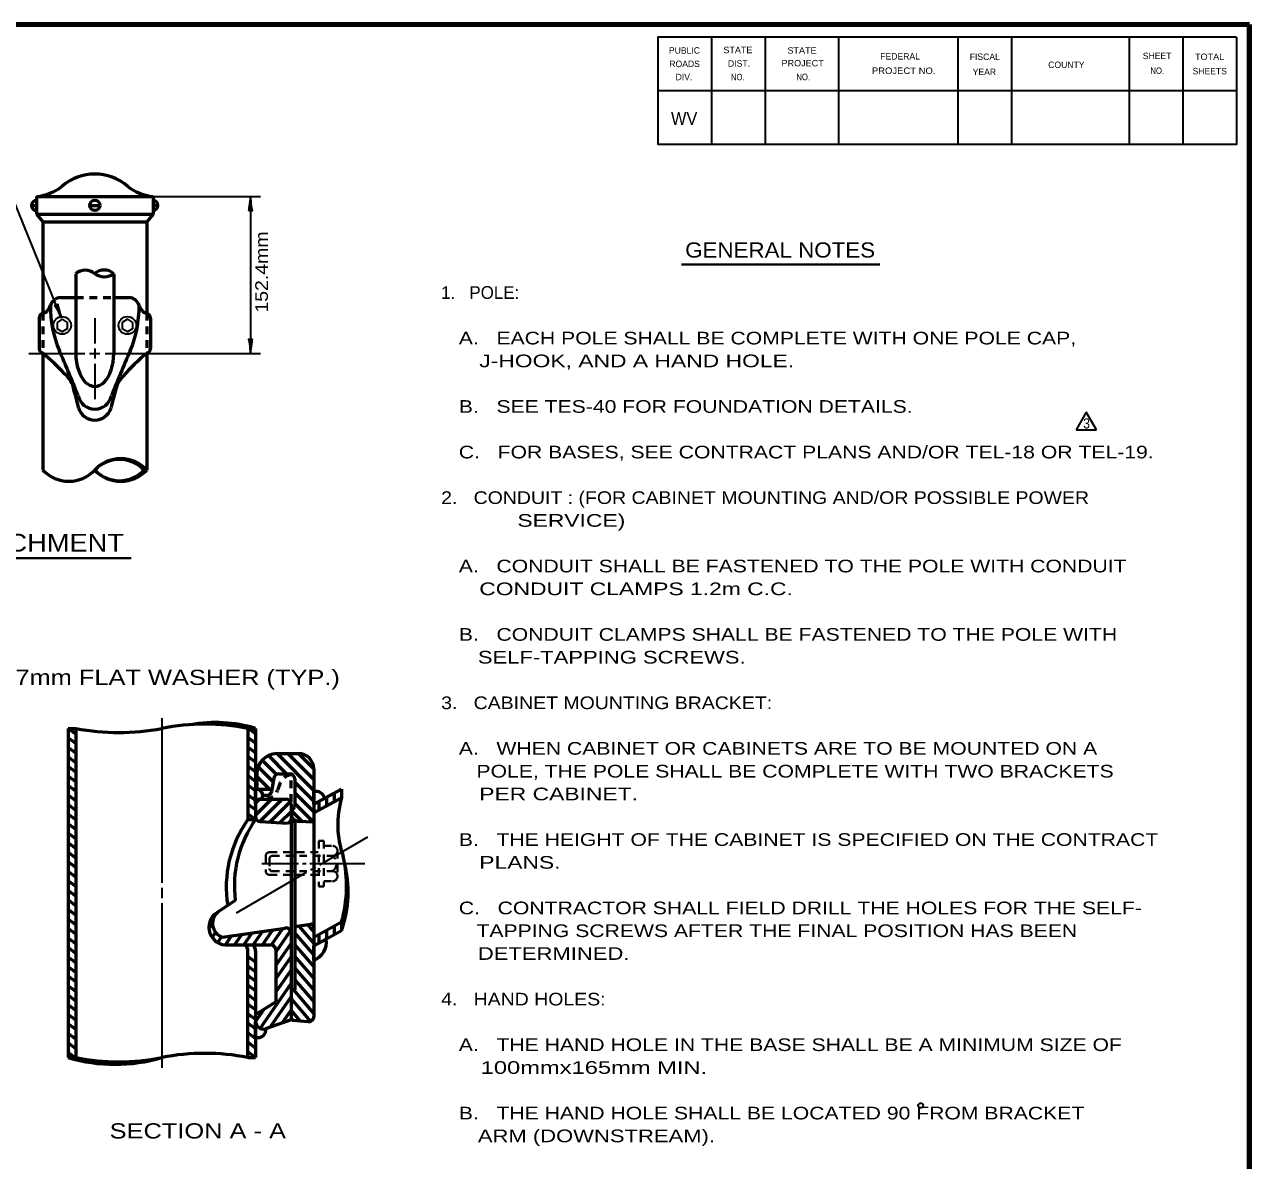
# Model space of a CAD drawing. Extents: x -32 to 824, y -12 to 532.
# Drawn here: x 527.1 to 817.5, y 256.1 to 525.2 of the extents above; entities that cross this region are included whole.
import ezdxf
from ezdxf.enums import TextEntityAlignment as Align

# ---------------------------------------------------------------- set-up
doc = ezdxf.new("R2010")
doc.units = 0
doc.header["$LTSCALE"] = 1.2
doc.linetypes.add('SHORT_DASHED', pattern=[2.7, 1.5, -1.2])
doc.layers.add('1', color=7, linetype='Continuous', lineweight=13)
doc.layers.add('61', color=7, linetype='Continuous', lineweight=35)

msp = doc.modelspace()

# ---------------------------------------------------------------- linework, layer by layer
at = {"layer": '1', "lineweight": 158}
msp.add_line((817.469, -0.873), (817.469, 525.227), dxfattribs=at)
at = {"layer": '1'}
msp.add_line((817.469, -0.873), (817.469, 525.227), dxfattribs=at)
at = {"layer": '1', "lineweight": 35}
for p, q in [((535.927, 455.696), (516.646, 503.069)), ((557.609, 484.487), (583.109, 484.487)), ((580.709, 484.487), (580.709, 447.287)), ((536.068, 455.42), (534.868, 454.67)), ((534.868, 454.67), (534.868, 453.17)), ((536.068, 455.42), (537.268, 454.67)), ((537.268, 454.67), (537.268, 453.17)), ((543.809, 455.687), (543.809, 449.669)), ((551.529, 455.415), (550.329, 454.665)), ((550.329, 454.665), (550.329, 453.165)), ((551.529, 455.415), (552.729, 454.665)), ((552.729, 454.665), (552.729, 453.165)), ((528.209, 447.287), (541.436, 447.287)), ((542.57, 447.287), (544.969, 447.287)), ((543.809, 448.468), (543.809, 446.07)), ((546.235, 447.287), (583.109, 447.287)), ((543.809, 444.869), (543.809, 436.487)), ((778.789, 433.358), (776.389, 429.202)), ((781.189, 429.202), (778.789, 433.358)), ((776.389, 429.202), (781.189, 429.202)), ((559.709, 360.887), (559.709, 321.887)), ((597.116, 326.182), (608.548, 332.782)), ((583.409, 326.452), (592.109, 326.452)), ((593.009, 326.452), (593.909, 326.452)), ((594.809, 326.452), (607.819, 326.452)), ((595.038, 324.982), (596.217, 325.663)), ((577.371, 314.782), (593.999, 324.382)), ((559.709, 320.687), (559.709, 318.287)), ((559.709, 317.087), (559.709, 278.087))]:
    msp.add_line(p, q, dxfattribs=at)
at = {"layer": '1', "lineweight": 53}
for p, q in [((528.816, 482.387), (529.709, 482.387)), ((530.009, 484.487), (557.609, 484.487)), ((530.009, 484.487), (530.009, 480.287)), ((542.901, 482.387), (544.701, 482.387)), ((557.609, 484.487), (557.609, 480.287)), ((557.909, 482.387), (558.753, 482.387)), ((530.009, 480.287), (557.609, 480.287)), ((530.009, 480.287), (531.509, 478.487)), ((557.609, 480.287), (556.109, 478.487)), ((531.509, 478.487), (556.109, 478.487)), ((531.509, 478.487), (531.509, 456.887)), ((556.109, 478.487), (556.109, 456.887)), ((539.309, 466.187), (539.309, 447.287)), ((548.309, 466.187), (548.309, 447.287)), ((535.656, 460.53), (539.309, 460.53)), ((548.309, 460.53), (551.962, 460.53)), ((530.609, 455.687), (530.609, 448.487)), ((557.009, 455.687), (557.009, 448.487)), ((531.509, 447.287), (531.509, 419.687)), ((556.109, 447.29), (556.109, 419.687)), ((537.509, 358.487), (537.509, 280.487)), ((537.509, 358.487), (539.309, 358.487)), ((539.309, 357.122), (537.509, 358.487)), ((539.309, 358.487), (539.309, 280.487)), ((581.909, 357.215), (580.109, 358.579)), ((580.109, 358.487), (581.909, 358.487)), ((580.109, 358.487), (580.109, 336.887)), ((539.309, 354.864), (537.509, 356.228)), ((581.909, 354.956), (580.109, 356.32)), ((539.309, 352.605), (537.509, 353.969)), ((539.309, 350.346), (537.509, 351.711)), ((581.909, 352.697), (580.109, 354.062)), ((581.909, 350.439), (580.109, 351.803)), ((584.941, 352.018), (589.272, 347.687)), ((587.009, 352.487), (592.109, 352.487)), ((587.018, 352.487), (595.709, 343.795)), ((589.563, 352.487), (595.709, 346.341)), ((592.109, 352.487), (595.709, 348.887)), ((539.309, 348.088), (537.509, 349.452)), ((581.909, 348.18), (580.109, 349.544)), ((582.51, 349.358), (586.091, 345.777)), ((583.477, 350.937), (586.865, 347.548)), ((595.709, 348.887), (595.709, 340.487)), ((539.309, 345.829), (537.509, 347.193)), ((581.909, 345.921), (580.109, 347.286)), ((582.209, 347.687), (582.209, 344.087)), ((582.209, 347.113), (585.236, 344.087)), ((586.242, 346.684), (585.726, 343.589)), ((587.426, 347.687), (590.009, 347.687)), ((591.209, 346.487), (591.209, 339.887)), ((591.209, 345.75), (595.709, 341.25)), ((539.309, 343.57), (537.509, 344.935)), ((539.309, 341.311), (537.509, 342.676)), ((581.909, 343.663), (580.109, 345.027)), ((581.909, 341.404), (580.109, 342.768)), ((582.209, 344.087), (585.809, 344.087)), ((584.543, 342.587), (583.618, 342.577)), ((591.209, 343.204), (595.709, 338.704)), ((595.709, 340.487), (602.309, 344.087)), ((600.509, 343.105), (600.509, 341.054)), ((602.309, 344.087), (602.309, 342.036)), ((539.309, 339.053), (537.509, 340.417)), ((581.909, 339.145), (580.109, 340.51)), ((585.655, 341.687), (581.909, 337.941)), ((582.078, 341.251), (582.552, 341.567)), ((582.426, 341.441), (582.268, 341.283)), ((588.2, 341.687), (582.915, 336.402)), ((583.109, 341.687), (589.109, 341.687)), ((590.147, 341.088), (585.327, 336.268)), ((590.309, 340.487), (590.309, 336.093)), ((591.209, 340.659), (595.709, 336.159)), ((595.709, 338.436), (602.309, 342.036)), ((596.909, 341.141), (596.909, 339.091)), ((598.709, 342.123), (598.709, 340.073)), ((539.309, 336.794), (537.509, 338.159)), ((581.909, 336.887), (580.109, 338.251)), ((580.109, 336.887), (581.909, 336.887)), ((590.309, 338.704), (587.745, 336.14)), ((590.309, 339.013), (592.85, 336.472)), ((539.309, 334.535), (537.509, 335.9)), ((583.046, 336.388), (589.362, 336.055)), ((591.209, 336.379), (590.309, 336.379)), ((590.309, 336.093), (590.309, 289.909)), ((592.014, 336.516), (595.709, 336.322)), ((539.309, 332.277), (537.509, 333.641)), ((539.309, 330.018), (537.509, 331.382)), ((539.309, 327.759), (537.509, 329.124)), ((539.309, 325.501), (537.509, 326.865)), ((539.309, 323.242), (537.509, 324.606)), ((539.309, 320.983), (537.509, 322.348)), ((539.309, 318.725), (537.509, 320.089)), ((539.309, 316.466), (537.509, 317.83)), ((577.109, 317.687), (573.312, 315.155)), ((539.309, 314.207), (537.509, 315.572)), ((539.309, 311.949), (537.509, 313.313)), ((539.309, 309.69), (537.509, 311.054)), ((570.874, 311.057), (571.71, 312.267)), ((574.109, 308.987), (588.933, 311.183)), ((583.515, 307.187), (585.973, 310.744)), ((585.693, 307.173), (588.41, 311.105)), ((591.721, 311.596), (595.021, 312.085)), ((592.138, 311.658), (595.709, 307.489)), ((594.234, 311.977), (595.748, 310.211)), ((595.709, 309.048), (602.309, 312.648)), ((598.709, 310.684), (598.709, 308.634)), ((600.509, 311.666), (600.509, 309.615)), ((602.309, 312.648), (602.309, 310.597)), ((539.309, 307.431), (537.509, 308.796)), ((571.614, 308.962), (572.434, 310.149)), ((572.953, 307.733), (573.876, 309.069)), ((574.763, 307.187), (576.223, 309.3)), ((576.951, 307.187), (578.661, 309.661)), ((579.139, 307.187), (581.098, 310.022)), ((581.327, 307.187), (583.536, 310.383)), ((586.709, 305.477), (590.191, 310.516)), ((591.209, 309.975), (595.709, 304.723)), ((595.709, 306.997), (602.309, 310.597)), ((595.709, 306.997), (598.609, 308.579)), ((596.909, 309.702), (596.909, 307.652)), ((539.309, 305.173), (537.509, 306.537)), ((574.709, 307.187), (585.509, 307.187)), ((580.109, 280.487), (580.109, 305.687)), ((581.909, 305.687), (581.909, 284.939)), ((586.709, 302.31), (590.309, 307.521)), ((586.709, 305.987), (586.709, 293.687)), ((591.209, 307.208), (595.709, 301.957)), ((595.709, 306.997), (595.709, 290.203)), ((595.709, 303.525), (595.709, 306.997)), ((539.309, 302.914), (537.509, 304.278)), ((539.309, 300.655), (537.509, 302.02)), ((581.909, 303.073), (580.109, 304.437)), ((581.909, 300.814), (580.109, 302.179)), ((586.709, 299.144), (590.309, 304.354)), ((591.209, 304.442), (595.709, 299.19)), ((539.309, 298.397), (537.509, 299.761)), ((581.909, 298.556), (580.109, 299.92)), ((586.709, 295.977), (590.309, 301.188)), ((591.209, 301.676), (595.709, 296.424)), ((539.309, 296.138), (537.509, 297.502)), ((581.909, 296.297), (580.109, 297.662)), ((582.97, 287.399), (590.309, 298.021)), ((591.209, 296.509), (590.309, 296.509)), ((590.895, 296.509), (595.709, 290.891)), ((591.209, 298.909), (595.709, 293.658)), ((539.309, 293.879), (537.509, 295.244)), ((581.909, 294.038), (580.109, 295.403)), ((581.909, 290.687), (586.709, 293.687)), ((585.385, 287.728), (590.309, 294.854)), ((590.309, 294.427), (594.901, 289.068)), ((539.309, 291.62), (537.509, 292.985)), ((539.309, 289.362), (537.509, 290.726)), ((581.909, 291.78), (580.109, 293.144)), ((581.909, 289.521), (580.109, 290.886)), ((581.909, 289.03), (583.924, 291.946)), ((588.29, 288.766), (590.309, 291.688)), ((590.309, 291.661), (592.428, 289.188)), ((539.309, 287.103), (537.509, 288.468)), ((581.909, 287.262), (580.109, 288.627)), ((581.909, 289.041), (581.909, 280.487)), ((581.91, 285.38), (581.909, 289.041)), ((581.91, 285.38), (581.909, 289.041)), ((584.315, 287.346), (590.441, 289.534)), ((590.309, 289.909), (590.707, 289.344)), ((590.707, 289.344), (594.4, 289.008)), ((539.309, 284.844), (537.509, 286.209)), ((581.909, 285.004), (580.109, 286.368)), ((584.315, 287.346), (584.413, 287.381)), ((539.309, 282.586), (537.509, 283.95)), ((539.099, 280.487), (537.509, 281.692)), ((581.909, 282.745), (580.109, 284.11)), ((581.909, 280.487), (580.109, 281.851)), ((537.509, 280.487), (539.309, 280.487)), ((580.109, 280.487), (581.909, 280.487))]:
    msp.add_line(p, q, dxfattribs=at)
at = {"layer": '1', "lineweight": 40}
for p, q in [((682.89, 468.357), (729.837, 468.357)), ((452.577, 398.821), (552.429, 398.821))]:
    msp.add_line(p, q, dxfattribs=at)
at = {"layer": '1', "linetype": 'SHORT_DASHED', "lineweight": 53}
for p, q in [((539.309, 460.53), (548.309, 460.53)), ((531.509, 456.887), (531.509, 447.287)), ((556.109, 456.887), (556.109, 447.287)), ((590.309, 341.078), (590.309, 347.478)), ((587.618, 345.103), (587.132, 343.803))]:
    msp.add_line(p, q, dxfattribs=at)
at = {"layer": '1', "linetype": 'SHORT_DASHED', "lineweight": 40}
for p, q in [((596.909, 331.852), (598.109, 331.852)), ((596.909, 331.852), (596.909, 321.052)), ((598.109, 331.852), (598.109, 321.052)), ((584.309, 328.252), (584.309, 324.652)), ((585.209, 329.152), (596.909, 329.152)), ((585.809, 328.252), (600.129, 328.252)), ((598.109, 330.652), (600.129, 330.652)), ((601.329, 329.452), (601.329, 323.452)), ((585.209, 327.652), (585.209, 325.252)), ((585.209, 323.752), (596.909, 323.752)), ((585.809, 324.652), (600.129, 324.652)), ((596.909, 321.052), (598.109, 321.052)), ((598.109, 322.252), (600.129, 322.252))]:
    msp.add_line(p, q, dxfattribs=at)
at = {"layer": '1', "lineweight": 158}
msp.add_lwpolyline([(817.469, 525.227), (25.769, 525.127), (25.869, -0.873)], dxfattribs=at)
at = {"layer": '1', "lineweight": 35}
for points in [[(537.268, 453.17), (536.068, 452.42), (534.868, 453.17)], [(552.729, 453.165), (551.529, 452.415), (550.329, 453.165)]]:
    msp.add_lwpolyline(points, dxfattribs=at)
at = {"layer": '1', "lineweight": 53}
for points in [[(581.909, 358.487), (581.909, 340.487), (581.909, 336.887)], [(581.909, 340.487), (581.909, 344.454), (581.94, 344.046)], [(598.322, 341.912), (595.709, 340.487), (595.709, 343.454), (595.709, 343.454)], [(583.402, 341.733), (583.277, 341.745), (582.52, 341.53), (582.678, 341.541), (582.441, 341.439), (582.316, 341.315), (582.407, 341.281), (582.124, 341.168), (581.955, 340.693)], [(583.204, 341.687), (583.109, 341.687), (583.407, 341.762)], [(595.709, 340.487), (595.709, 338.436), (595.709, 309.048), (595.709, 306.997)], [(591.209, 336.379), (591.209, 311.002), (591.209, 296.509)]]:
    msp.add_lwpolyline(points, dxfattribs=at)
msp.add_circle((543.801, 482.389), 1.2, dxfattribs=at)
at = {"layer": '1', "lineweight": 35}
for centre, radius in [((536.084, 453.953), 2.1), ((551.535, 453.944), 2.1), ((739.551, 269.121), 0.573)]:
    msp.add_circle(centre, radius, dxfattribs=at)
at = {"layer": '1', "lineweight": 53}
for centre, radius, start, end in [((543.809, 477.854), 11.934, 49.18722, 130.81278), ((528.902, 495.954), 11.521, 275.5142, 308.08862), ((558.716, 495.954), 11.521, 231.91138, 264.4858), ((530.016, 482.355), 1.2, 90.3199, 269.6801), ((557.553, 482.355), 1.2, 272.67956, 87.32044), ((541.559, 463.582), 3.442, 49.17959, 130.82041), ((546.059, 463.708), 3.347, 47.76241, 132.23758), ((546.059, 469.455), 3.968, 235.45601, 304.54399), ((535.812, 457.915), 2.619, 93.41837, 162.8601), ((551.806, 457.915), 2.619, 17.1399, 86.58162), ((531.877, 455.619), 1.27, 93.07015, 176.92984), ((530.724, 459.316), 2.66, 294.0674, 346.32146), ((560.498, 458.369), 27.19, 179.33091, 202.67617), ((527.121, 458.369), 27.19, 337.32383, 0.66909), ((556.894, 459.316), 2.66, 193.67854, 245.9326), ((555.741, 455.619), 1.27, 3.07016, 86.92985), ((531.877, 448.555), 1.27, 183.07016, 253.15341), ((499.183, 408.351), 50.646, 42.29957, 50.33685), ((318.148, 350.377), 238.14, 21.39177, 24.17121), ((774.499, 348.265), 243.593, 155.85991, 158.57712), ((588.435, 408.351), 50.646, 129.66315, 138.49633), ((555.741, 448.555), 1.27, 286.84659, 356.92984), ((532.929, 437.706), 6.014, 9.48157, 51.86654), ((554.93, 437.31), 6.344, 133.87214, 169.50589), ((445.933, 412.492), 96.552, 13.13509, 15.74771), ((641.685, 412.492), 96.552, 163.98892, 166.86491), ((543.809, 438.143), 4.03, 193.00171, 346.99829), ((543.809, 435.517), 4, 195.72161, 344.27839), ((549.959, 413.953), 8.408, 42.99091, 137.00909), ((549.649, 414.104), 8.079, 43.44505, 136.28697), ((537.659, 425.42), 8.408, 222.99091, 317.00909), ((549.959, 425.42), 8.408, 222.99091, 317.00909), ((549.675, 425.23), 8.07, 223.38031, 316.35171), ((549.509, 409.651), 52.171, 258.72544, 281.27456), ((569.909, 307.322), 52.171, 78.72544, 101.27456), ((572.351, 325.857), 34.001, 73.67307, 99.88388), ((587.009, 347.687), 4.8, 90, 180), ((592.109, 348.887), 3.6, 0, 90), ((587.426, 346.487), 1.2, 90, 170.53768), ((590.009, 346.487), 1.2, 0, 90), ((582.099, 342.535), 1.52, 329.43434, 96.01658), ((584.543, 343.787), 1.2, 270, 350.53836), ((596.288, 341.525), 2.014, 10.62414, 106.70314), ((583.109, 340.487), 1.2, 90, 180), ((583.525, 340.07), 1.669, 104.44111, 165.55889), ((580.742, 341.696), 1.535, 320.82126, 345.1698), ((582.982, 340.481), 1.062, 132.01704, 165.33257), ((586.526, 337.687), 5.527, 138.35366, 144.36072), ((583.205, 340.537), 1.214, 107.64312, 154.39534), ((583.079, 340.866), 0.817, 97.5146, 146.7228), ((582.466, 341.647), 0.211, 260.06059, 322.47031), ((582.292, 342.746), 1.252, 278.38082, 293.49085), ((589.109, 340.487), 1.2, 0, 90), ((590.465, 340.072), 0.767, 260.57519, 346.02951), ((623.81, 335.663), 22.425, 163.48944, 199.55179), ((602.511, 320.851), 27.55, 144.40401, 189.11494), ((603.97, 321.171), 27.086, 144.53567, 187.39184), ((583.109, 337.586), 1.2, 180, 266.98501), ((589.409, 336.954), 0.9, 266.98584, 0), ((592.109, 338.314), 1.8, 180, 266.9852), ((572, 321.127), 31.473, 344.37008, 12.90873), ((575.954, 319.759), 27.902, 340.83222, 14.49037), ((575.042, 311.352), 4.178, 114.45413, 265.43129), ((575.136, 312.255), 3.426, 122.16994, 252.55173), ((589.109, 309.996), 1.2, 0, 98.42688), ((591.809, 311.002), 0.6, 98.42904, 180), ((595.109, 311.491), 0.6, 0, 98.42709), ((594.161, 307.772), 4.521, 290.03142, 10.27964), ((577.961, 305.697), 2.148, 359.71435, 43.88847), ((579.761, 305.697), 2.148, 359.71435, 43.88847), ((585.509, 305.987), 1.2, 0, 90), ((583.709, 289.041), 1.8, 180, 288.30571), ((583.709, 289.041), 1.8, 180, 288.30571), ((590.909, 289.909), 0.6, 180, 250.34668), ((594.509, 290.203), 1.2, 264.79006, 0), ((582.555, 287.044), 1.785, 248.82416, 9.72636), ((582.555, 287.044), 1.785, 248.82416, 9.72636), ((548.609, 318.289), 39.399, 253.63622, 286.36377), ((549.509, 331.651), 52.171, 258.72544, 281.27456), ((569.909, 229.322), 52.171, 78.72544, 101.27456)]:
    msp.add_arc(centre, radius, start, end, dxfattribs=at)
at = {"layer": '1', "linetype": 'SHORT_DASHED', "lineweight": 53}
for centre, radius, start, end in [((590.628, 344.404), 3.09, 95.92601, 166.92161), ((583.921, 345.145), 3.481, 276.48502, 337.3181)]:
    msp.add_arc(centre, radius, start, end, dxfattribs=at)
at = {"layer": '1', "linetype": 'SHORT_DASHED', "lineweight": 40}
for centre, radius, start, end in [((585.209, 328.252), 0.9, 90, 180), ((585.809, 327.652), 0.6, 90, 180), ((600.129, 329.452), 1.2, 0, 90), ((600.129, 329.452), 1.2, 270, 0), ((598.897, 326.452), 2.182, 304.40161, 55.59839), ((585.809, 325.252), 0.6, 180, 270), ((585.209, 324.652), 0.9, 180, 270), ((600.129, 323.452), 1.2, 0, 90), ((600.129, 323.452), 1.2, 270, 0)]:
    msp.add_arc(centre, radius, start, end, dxfattribs=at)
at = {"layer": '1', "lineweight": 40}
for centre, major_axis, ratio, start_param, end_param in [((580.455, 483.142), (0.211, 2.108), 0.07063, 3.1407148, 5.41811), ((581.041, 483.177), (-0.187, 2.143), 0.122415, 0.8963533, 3.1415927), ((535.126, 456.784), (0.981, -1.914), 0.122415, 0.8963533, 3.1415927), ((535.655, 457.037), (-0.599, 2.032), 0.07063, 6.2823074, 8.5597026), ((580.378, 448.596), (0.187, -2.143), 0.122415, 0.8963533, 3.1415927), ((580.963, 448.631), (-0.211, -2.108), 0.07063, 3.1407148, 5.41811)]:
    msp.add_ellipse(centre, major_axis=major_axis, ratio=ratio, start_param=start_param, end_param=end_param, dxfattribs=at)
at = {"layer": '1', "lineweight": 53}
msp.add_ellipse((543.809, 447.287), major_axis=(0, 7.801), ratio=0.576878, start_param=1.5707963, end_param=4.712389, dxfattribs=at)
at = {"layer": '61'}
for p, q in [((689.969, 522.227), (689.969, 496.827)), ((702.669, 522.227), (702.669, 496.827)), ((720.069, 522.227), (720.069, 496.827)), ((748.369, 522.227), (748.369, 496.827)), ((761.069, 522.227), (761.069, 496.827)), ((788.969, 522.227), (788.969, 496.827)), ((801.669, 522.227), (801.669, 496.827)), ((814.369, 509.527), (677.269, 509.527))]:
    msp.add_line(p, q, dxfattribs=at)
for points in [[(814.369, 522.227), (677.269, 522.227), (677.269, 496.827)], [(814.369, 522.227), (814.369, 496.827), (677.269, 496.827)]]:
    msp.add_lwpolyline(points, dxfattribs=at)

# ---------------------------------------------------------------- texts
at = {"layer": '1'}
for s, height, width, p in [('WV', 3.048, 0.95, (680.369, 501.427)), ('GENERAL NOTES', 3.6, 1.1, (683.721, 470.01)), ('   A.   EACH POLE SHALL BE COMPLETE WITH ONE POLE CAP,', 3, 1.25, (625.899, 449.437)), ('      J-HOOK, AND A HAND HOLE.', 3, 1.35, (625.899, 444.037)), ('   B.   SEE TES-40 FOR FOUNDATION DETAILS.', 3, 1.25, (625.899, 433.237)), ('3', 2.4, 0.9, (778.044, 429.526)), ('   C.   FOR BASES, SEE CONTRACT PLANS AND/OR TEL-18 OR TEL-19.', 3, 1.25, (625.899, 422.437)), ('2.   CONDUIT : (FOR CABINET MOUNTING AND/OR POSSIBLE POWER', 3, 1.15, (625.899, 411.637)), ('            SERVICE)', 3, 1.35, (625.899, 406.237)), ('   A.   CONDUIT SHALL BE FASTENED TO THE POLE WITH CONDUIT', 3, 1.25, (625.899, 395.437)), ('      CONDUIT CLAMPS 1.2m C.C.', 3, 1.35, (625.899, 390.037)), ('   B.   CONDUIT CLAMPS SHALL BE FASTENED TO THE POLE WITH', 3, 1.25, (625.899, 379.237)), ('      SELF-TAPPING SCREWS.', 3, 1.3, (625.899, 373.837)), ('12.7mm FLAT WASHER (TYP.)', 3.6, 1.25, (516.627, 368.764)), ('3.   CABINET MOUNTING BRACKET:', 3, 1.15, (625.899, 363.037)), ('   A.   WHEN CABINET OR CABINETS ARE TO BE MOUNTED ON A', 3, 1.25, (625.899, 352.237)), ('      POLE, THE POLE SHALL BE COMPLETE WITH TWO BRACKETS', 3, 1.25, (625.899, 346.837)), ('      PER CABINET.', 3, 1.35, (625.899, 341.437)), ('   B.   THE HEIGHT OF THE CABINET IS SPECIFIED ON THE CONTRACT', 3, 1.25, (625.899, 330.637)), ('      PLANS.', 3, 1.35, (625.899, 325.237)), ('   C.   CONTRACTOR SHALL FIELD DRILL THE HOLES FOR THE SELF-', 3, 1.25, (625.899, 314.437)), ('      TAPPING SCREWS AFTER THE FINAL POSITION HAS BEEN', 3, 1.25, (625.899, 309.037)), ('      DETERMINED.', 3, 1.3, (625.899, 303.637)), ('4.   HAND HOLES:', 3, 1.15, (625.899, 292.837)), ('   A.   THE HAND HOLE IN THE BASE SHALL BE A MINIMUM SIZE OF', 3, 1.25, (625.899, 282.037)), ('      100mmx165mm MIN.', 3, 1.4, (625.899, 276.637)), ('   B.   THE HAND HOLE SHALL BE LOCATED 90 FROM BRACKET', 3, 1.25, (625.899, 265.837)), ('SECTION A - A', 3.6, 1.25, (547.326, 261.321)), ('      ARM (DOWNSTREAM).', 3, 1.3, (625.899, 260.437))]:
    msp.add_text(s, height=height, dxfattribs=dict(at, width=width)).set_placement(p)
at = {"layer": '1', "width": 1.15}
msp.add_text('152.4mm', height=3, rotation=90, dxfattribs=at).set_placement((584.839, 456.966))
at = {"layer": '1'}
msp.add_text('1.   POLE:', height=3, dxfattribs=at).set_placement((625.899, 460.237))
at = {"layer": '1', "width": 1.15}
msp.add_text('TWO BOLT ARM ATTACHMENT', height=4.2, dxfattribs=at).set_placement((502.821, 400.361), align=Align.CENTER)
at = {"layer": '61'}
for s, height, rotation, p in [('PUBLIC', 1.525, 0.033, (679.869, 518.327)), ('DIST.', 1.525, 0.056, (693.869, 515.227)), ('FEDERAL', 1.523, 0.007, (729.969, 516.927)), ('FISCAL', 1.525, 359.942, (751.169, 516.827)), ('SHEET', 1.525, 0.059, (792.169, 517.027)), ('ROADS', 1.525, 0.124, (679.969, 515.127)), ('YEAR', 1.523, 0.105, (751.869, 513.227)), ('COUNTY', 1.523, 0.069, (769.769, 514.927)), ('SHEETS', 1.523, 359.959, (803.969, 513.427)), ('DIV.', 1.525, 359.932, (681.469, 512.027))]:
    msp.add_text(s, height=height, rotation=rotation, dxfattribs=at).set_placement(p)
for s, rotation, width, p in [('STATE', 0.059, 1.05, (692.769, 518.427)), ('STATE', 0.059, 1.05, (707.969, 518.327)), ('PROJECT', 359.908, 1.05, (706.569, 515.327)), ('TOTAL', 359.926, 1.05, (804.569, 516.827)), ('PROJECT NO.', 359.922, 1.1, (727.969, 513.527)), ('NO.', 359.852, 0.9, (793.969, 513.527)), ('NO.', 359.852, 0.9, (694.569, 512.027)), ('NO.', 0.225, 0.9, (710.069, 512.027))]:
    msp.add_text(s, height=1.525, rotation=rotation, dxfattribs=dict(at, width=width)).set_placement(p)

doc.saveas('drawing.dxf')
